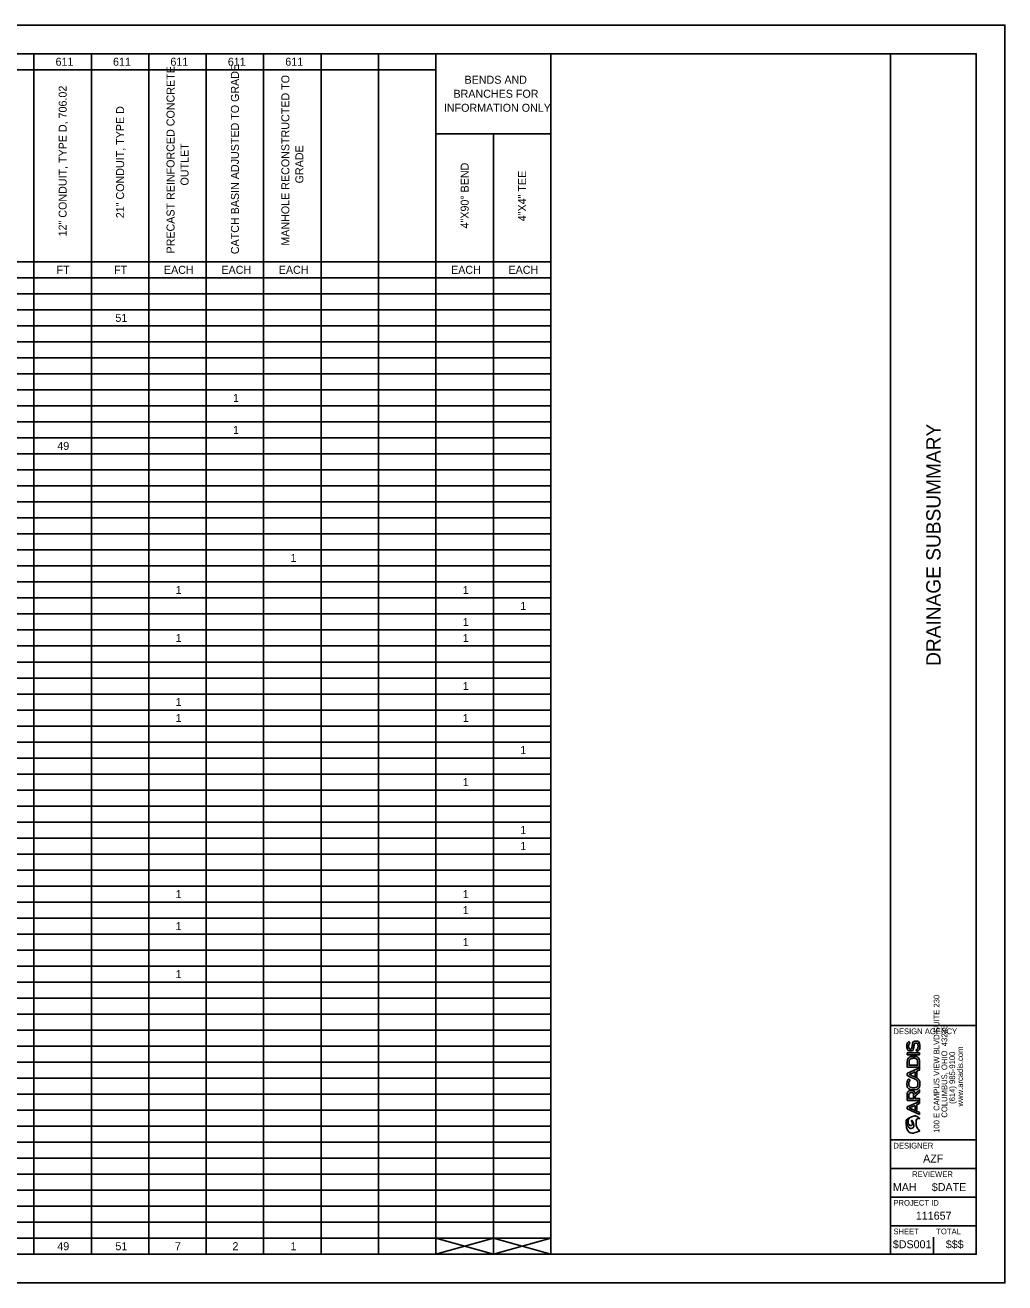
# Model space of a CAD drawing. Extents: x 0 to 34, y 0 to 22.
# Drawn here: x 16.86 to 34, y 0 to 22 of the extents above; entities that cross this region are included whole.
import ezdxf

# ---------------------------------------------------------------- set-up
doc = ezdxf.new("R2010")
doc.units = 0
for name, color, linetype in [('SH_Border', 7, 'Continuous'), ('SH_Cut_Line', 7, 'Continuous'), ('SH_Data', 7, 'Continuous'), ('SN_P_Cantilever_Overhead', 7, 'Continuous')]:
    doc.layers.add(name, color=color, linetype=linetype)

msp = doc.modelspace()

# ---------------------------------------------------------------- linework, layer by layer
at = {"layer": 'SH_Border'}
for p, q in [((32, 0.5), (32, 21.5)), ((32, 4.5), (33.5, 4.5)), ((32, 2.5), (33.5, 2.5)), ((32, 2), (33.5, 2)), ((32, 1.5), (33.5, 1.5)), ((32, 1), (33.5, 1))]:
    msp.add_line(p, q, dxfattribs=at)
msp.add_lwpolyline([(1.5, 21.5), (33.5, 21.5), (33.5, 0.5), (1.5, 0.5)], close=True, dxfattribs=at)
at = {"layer": 'SH_Cut_Line'}
msp.add_lwpolyline([(0, 0), (34, 0), (34, 22), (0, 22)], close=True, dxfattribs=at)
at = {"layer": 'SH_Data'}
for p, q in [((32.507, 4.022), (32.292, 4.022)), ((32.292, 4.022), (32.292, 3.988)), ((32.292, 3.988), (32.507, 3.988)), ((32.507, 3.988), (32.507, 4.022)), ((32.75, 3.5), (32.75, 3.5)), ((32.75, 3.5), (32.75, 3.5)), ((32.507, 3.175), (32.292, 3.079)), ((32.328, 3.06), (32.431, 3.105)), ((32.431, 3.105), (32.431, 3.034)), ((32.462, 3.119), (32.507, 3.139)), ((32.462, 3.02), (32.462, 3.119)), ((32.507, 3.139), (32.507, 3.175)), ((32.292, 3.079), (32.292, 3.041)), ((32.292, 3.041), (32.507, 2.945)), ((32.507, 2.981), (32.328, 3.06)), ((32.431, 3.034), (32.462, 3.02)), ((32.507, 2.945), (32.507, 2.981)), ((32.375, 0.675), (32.375, 0.675)), ((32.75, 0.5), (32.75, 0.8))]:
    msp.add_line(p, q, dxfattribs=at)
for points, degree in [([(32.34, 4.193), (32.325, 4.183), (32.316, 4.163), (32.316, 4.14), (32.316, 4.111), (32.328, 4.09), (32.348, 4.09), (32.369, 4.09), (32.375, 4.114), (32.379, 4.143), (32.385, 4.187), (32.398, 4.229), (32.446, 4.229), (32.494, 4.229), (32.512, 4.185), (32.512, 4.14), (32.512, 4.099), (32.5, 4.067), (32.463, 4.047), (32.463, 4.047), (32.446, 4.073), (32.446, 4.073), (32.472, 4.088), (32.482, 4.115), (32.482, 4.14), (32.482, 4.166), (32.473, 4.195), (32.446, 4.195), (32.422, 4.195), (32.414, 4.17), (32.41, 4.14), (32.405, 4.097), (32.394, 4.056), (32.348, 4.056), (32.303, 4.056), (32.286, 4.1), (32.286, 4.139), (32.286, 4.17), (32.293, 4.201), (32.322, 4.22), (32.322, 4.22), (32.34, 4.193), (32.34, 4.193), (32.34, 4.193), (32.34, 4.193), (32.34, 4.193)], 3), ([(32.292, 3.772), (32.292, 3.772), (32.507, 3.772), (32.507, 3.772), (32.507, 3.772), (32.507, 3.854), (32.507, 3.854), (32.507, 3.929), (32.452, 3.963), (32.398, 3.962), (32.345, 3.961), (32.292, 3.927), (32.292, 3.854)], 3), ([(32.292, 3.664), (32.292, 3.664), (32.292, 3.626), (32.292, 3.626), (32.292, 3.626), (32.432, 3.563), (32.432, 3.563), (32.432, 3.563), (32.432, 3.563), (32.432, 3.563), (32.445, 3.557), (32.453, 3.549), (32.456, 3.547), (32.471, 3.532), (32.479, 3.51), (32.479, 3.49), (32.479, 3.434), (32.44, 3.411), (32.401, 3.41), (32.361, 3.41), (32.321, 3.435), (32.321, 3.49), (32.321, 3.51), (32.328, 3.53), (32.343, 3.545), (32.343, 3.545), (32.321, 3.569), (32.321, 3.569), (32.299, 3.547), (32.288, 3.519), (32.288, 3.49), (32.288, 3.413), (32.345, 3.376), (32.401, 3.376), (32.458, 3.376), (32.512, 3.412), (32.512, 3.49), (32.512, 3.52), (32.502, 3.549), (32.48, 3.571), (32.48, 3.571), (32.466, 3.584), (32.446, 3.593), (32.446, 3.593), (32.44, 3.596), (32.44, 3.596), (32.44, 3.596), (32.425, 3.602), (32.425, 3.602), (32.425, 3.602), (32.425, 3.602), (32.425, 3.602), (32.425, 3.602), (32.328, 3.645), (32.328, 3.645), (32.328, 3.645), (32.431, 3.69), (32.431, 3.69), (32.431, 3.69), (32.431, 3.619), (32.431, 3.619), (32.431, 3.619), (32.462, 3.605), (32.462, 3.605), (32.462, 3.605), (32.462, 3.704), (32.462, 3.704), (32.462, 3.704), (32.507, 3.724), (32.507, 3.724), (32.507, 3.724), (32.507, 3.76), (32.507, 3.76), (32.507, 3.76), (32.292, 3.664), (32.292, 3.664), (32.292, 3.664), (32.292, 3.664), (32.292, 3.664)], 3), ([(32.292, 3.854), (32.292, 3.854), (32.292, 3.772), (32.292, 3.772)], 2), ([(32.474, 3.806), (32.474, 3.806), (32.325, 3.806), (32.325, 3.806)], 2), ([(32.325, 3.806), (32.325, 3.806), (32.325, 3.854), (32.325, 3.854), (32.325, 3.905), (32.361, 3.927), (32.398, 3.928), (32.435, 3.929), (32.474, 3.906), (32.474, 3.854), (32.474, 3.854), (32.474, 3.806), (32.474, 3.806)], 3), ([(32.43, 3.305), (32.423, 3.348), (32.393, 3.364), (32.362, 3.364), (32.326, 3.364), (32.292, 3.337), (32.292, 3.288), (32.292, 3.254), (32.292, 3.221), (32.292, 3.187), (32.292, 3.187), (32.507, 3.187), (32.507, 3.187), (32.507, 3.187), (32.507, 3.222), (32.507, 3.222), (32.507, 3.222), (32.433, 3.222), (32.433, 3.222), (32.433, 3.222), (32.433, 3.267), (32.433, 3.267), (32.433, 3.267), (32.507, 3.333), (32.507, 3.333), (32.507, 3.333), (32.507, 3.373), (32.507, 3.373)], 3), ([(32.323, 3.288), (32.323, 3.316), (32.344, 3.329), (32.363, 3.329), (32.383, 3.329), (32.402, 3.316), (32.402, 3.287), (32.402, 3.287), (32.402, 3.222), (32.402, 3.222), (32.402, 3.222), (32.323, 3.222), (32.323, 3.222)], 3), ([(32.507, 3.373), (32.507, 3.373), (32.43, 3.305), (32.43, 3.305)], 2), ([(32.323, 3.222), (32.323, 3.222), (32.323, 3.288), (32.323, 3.288)], 2), ([(32.272, 2.786), (32.282, 2.575), (32.514, 2.656), (32.514, 2.656), (32.494, 2.674), (32.446, 2.734), (32.446, 2.817), (32.446, 2.817), (32.446, 2.817), (32.446, 2.818), (32.446, 2.858), (32.48, 2.881), (32.514, 2.872), (32.514, 2.872), (32.441, 2.935), (32.357, 2.9), (32.329, 2.888), (32.309, 2.857), (32.309, 2.821), (32.309, 2.808), (32.311, 2.795), (32.316, 2.782), (32.329, 2.752), (32.356, 2.748), (32.369, 2.754), (32.378, 2.759), (32.383, 2.768), (32.383, 2.777), (32.383, 2.779), (32.383, 2.781), (32.383, 2.782), (32.378, 2.813), (32.364, 2.826), (32.364, 2.833), (32.364, 2.834), (32.364, 2.835), (32.365, 2.835), (32.368, 2.84), (32.383, 2.836), (32.398, 2.796), (32.402, 2.787), (32.407, 2.769), (32.407, 2.752), (32.407, 2.732), (32.401, 2.712), (32.38, 2.706), (32.343, 2.693), (32.298, 2.738), (32.293, 2.804), (32.292, 2.807), (32.292, 2.812), (32.292, 2.815), (32.292, 2.849), (32.307, 2.873), (32.317, 2.885), (32.294, 2.871), (32.273, 2.842), (32.272, 2.796), (32.272, 2.796), (32.272, 2.792), (32.272, 2.786), (32.272, 2.786), (32.272, 2.786), (32.272, 2.786)], 3)]:
    msp.add_open_spline(points, degree=degree, dxfattribs=at)
at = {"layer": 'SN_P_Cantilever_Overhead'}
for p, q in [((1.5, 21.5), (26.057, 21.5)), ((17.015, 21.5), (17.015, 0.501)), ((18.019, 21.5), (18.019, 0.501)), ((19.024, 21.5), (19.024, 0.501)), ((20.029, 21.5), (20.029, 0.501)), ((21.033, 21.5), (21.033, 0.501)), ((22.038, 21.5), (22.038, 0.501)), ((23.043, 21.5), (23.043, 0.501)), ((24.047, 21.5), (24.047, 0.501)), ((26.057, 21.5), (26.057, 0.501)), ((8.977, 21.22), (24.047, 21.22)), ((24.047, 20.1), (26.057, 20.1)), ((25.052, 20.1), (25.052, 0.501)), ((8.977, 17.86), (26.057, 17.86)), ((1.5, 17.58), (26.057, 17.58)), ((1.5, 17.3), (26.057, 17.3)), ((1.5, 17.02), (26.057, 17.02)), ((1.5, 16.74), (26.057, 16.74)), ((1.5, 16.46), (26.057, 16.46)), ((1.5, 16.18), (26.057, 16.18)), ((1.5, 15.9), (26.057, 15.9)), ((1.5, 15.62), (26.057, 15.62)), ((1.5, 15.34), (26.057, 15.34)), ((1.5, 15.06), (26.057, 15.06)), ((1.5, 14.78), (26.057, 14.78)), ((1.5, 14.5), (26.057, 14.5)), ((1.5, 14.22), (26.057, 14.22)), ((1.5, 13.94), (26.057, 13.94)), ((1.5, 13.66), (26.057, 13.66)), ((1.5, 13.38), (26.057, 13.38)), ((1.5, 13.1), (26.057, 13.1)), ((1.5, 12.82), (26.057, 12.82)), ((1.5, 12.54), (26.057, 12.54)), ((1.5, 12.26), (26.057, 12.26)), ((1.5, 11.98), (26.057, 11.98)), ((1.5, 11.7), (26.057, 11.7)), ((1.5, 11.42), (26.057, 11.42)), ((1.5, 11.14), (26.057, 11.14)), ((1.5, 10.86), (26.057, 10.86)), ((1.5, 10.58), (26.057, 10.58)), ((1.5, 10.3), (26.057, 10.3)), ((1.5, 10.02), (26.057, 10.02)), ((1.5, 9.74), (26.057, 9.74)), ((1.5, 9.46), (26.057, 9.46)), ((1.5, 9.18), (26.057, 9.18)), ((1.5, 8.9), (26.057, 8.9)), ((1.5, 8.62), (26.057, 8.62)), ((1.5, 8.34), (26.057, 8.34)), ((1.5, 8.06), (26.057, 8.06)), ((1.5, 7.78), (26.057, 7.78)), ((1.5, 7.5), (26.057, 7.5)), ((1.5, 7.221), (26.057, 7.221)), ((1.5, 6.941), (26.057, 6.941)), ((1.5, 6.661), (26.057, 6.661)), ((1.5, 6.381), (26.057, 6.381)), ((1.5, 6.101), (26.057, 6.101)), ((1.5, 5.821), (26.057, 5.821)), ((1.5, 5.541), (26.057, 5.541)), ((1.5, 5.261), (26.057, 5.261)), ((1.5, 4.981), (26.057, 4.981)), ((1.5, 4.701), (26.057, 4.701)), ((1.5, 4.421), (26.057, 4.421)), ((1.5, 4.141), (26.057, 4.141)), ((1.5, 3.861), (26.057, 3.861)), ((1.5, 3.581), (26.057, 3.581)), ((1.5, 3.301), (26.057, 3.301)), ((1.5, 3.021), (26.057, 3.021)), ((1.5, 2.741), (26.057, 2.741)), ((1.5, 2.461), (26.057, 2.461)), ((1.5, 2.181), (26.057, 2.181)), ((1.5, 1.901), (26.057, 1.901)), ((1.5, 1.621), (26.057, 1.621)), ((1.5, 1.341), (26.057, 1.341)), ((1.5, 1.061), (26.057, 1.061)), ((1.5, 0.781), (26.057, 0.781)), ((24.047, 0.501), (25.052, 0.781)), ((24.047, 0.781), (25.052, 0.501)), ((25.052, 0.501), (26.057, 0.781)), ((25.052, 0.781), (26.057, 0.501)), ((1.5, 0.501), (26.057, 0.501))]:
    msp.add_line(p, q, dxfattribs=at)

# ---------------------------------------------------------------- texts
at = {"layer": 'SH_Data'}
for s, height, p in [('DRAINAGE SUBSUMMARY', 0.25, (32.875, 10.792)), ('100 E CAMPUS VIEW BLVD SUITE 230', 0.1, (32.855, 2.623)), ('COLUMBUS, OHIO  43235', 0.1, (32.992, 2.89)), ('(614) 985-9100', 0.1, (33.13, 3.13)), ('www.arcadis.com', 0.1, (33.268, 3.085))]:
    msp.add_text(s, height=height, rotation=90, dxfattribs=at).set_placement(p)
for s, height, p in [('DESIGN AGENCY', 0.1, (32.05, 4.35)), ('DESIGNER', 0.1, (32.05, 2.35)), ('AZF', 0.14, (32.57, 2.105)), ('REVIEWER', 0.1, (32.378, 1.85)), ('MAH', 0.14, (32.041, 1.605)), ('$DATE', 0.14, (32.722, 1.605)), ('PROJECT ID', 0.1, (32.05, 1.35)), ('111657', 0.14, (32.443, 1.105)), ('SHEET', 0.1, (32.05, 0.85)), ('TOTAL', 0.1, (32.8, 0.85)), ('$DS001', 0.14, (32.04, 0.605)), ('$$$', 0.14, (32.967, 0.605))]:
    msp.add_text(s, height=height, dxfattribs=at).set_placement(p)
at = {"layer": 'SN_P_Cantilever_Overhead'}
for s, p in [('611', (17.393, 21.29)), ('611', (18.398, 21.29)), ('611', (19.402, 21.29)), ('611', (20.407, 21.29)), ('611', (21.412, 21.29)), ('BENDS AND ', (24.548, 20.975)), ('BRANCHES FOR ', (24.354, 20.73)), ('INFORMATION ONLY', (24.186, 20.485)), ('FT', (17.411, 17.65)), ('FT', (18.416, 17.65)), ('EACH', (19.289, 17.65)), ('EACH', (20.294, 17.65)), ('EACH', (21.298, 17.65)), ('EACH', (24.312, 17.65)), ('EACH', (25.317, 17.65)), ('51', (18.44, 16.81)), ('1', (20.498, 15.41)), ('1', (20.498, 14.85)), ('49', (17.423, 14.57)), ('1', (21.503, 12.61)), ('1', (19.494, 12.05)), ('1', (24.517, 12.05)), ('1', (25.522, 11.77)), ('1', (24.517, 11.49)), ('1', (19.494, 11.21)), ('1', (24.517, 11.21)), ('1', (24.517, 10.37)), ('1', (19.494, 10.09)), ('1', (19.494, 9.81)), ('1', (24.517, 9.81)), ('1', (25.522, 9.25)), ('1', (24.517, 8.69)), ('1', (25.522, 7.85)), ('1', (25.522, 7.57)), ('1', (19.494, 6.731)), ('1', (24.517, 6.731)), ('1', (24.517, 6.451)), ('1', (19.494, 6.171)), ('1', (24.517, 5.891)), ('1', (19.494, 5.331)), ('49', (17.423, 0.571)), ('51', (18.44, 0.571)), ('7', (19.481, 0.571)), ('2', (20.487, 0.571)), ('1', (21.503, 0.571))]:
    msp.add_text(s, height=0.14, dxfattribs=at).set_placement(p)
for s, p in [('PRECAST REINFORCED CONCRETE ', (19.474, 18.006)), ('CATCH BASIN ADJUSTED TO GRADE', (20.601, 17.994)), ('12" CONDUIT, TYPE D, 706.02', (17.587, 18.305)), ('MANHOLE RECONSTRUCTED TO ', (21.483, 18.143)), ('21" CONDUIT, TYPE D', (18.592, 18.623)), ('OUTLET', (19.719, 19.195)), ('GRADE', (21.728, 19.232)), ('4"X90° BEND', (24.62, 18.444)), ('4"X4" TEE', (25.624, 18.57))]:
    msp.add_text(s, height=0.14, rotation=90, dxfattribs=at).set_placement(p)

doc.saveas('drawing.dxf')
